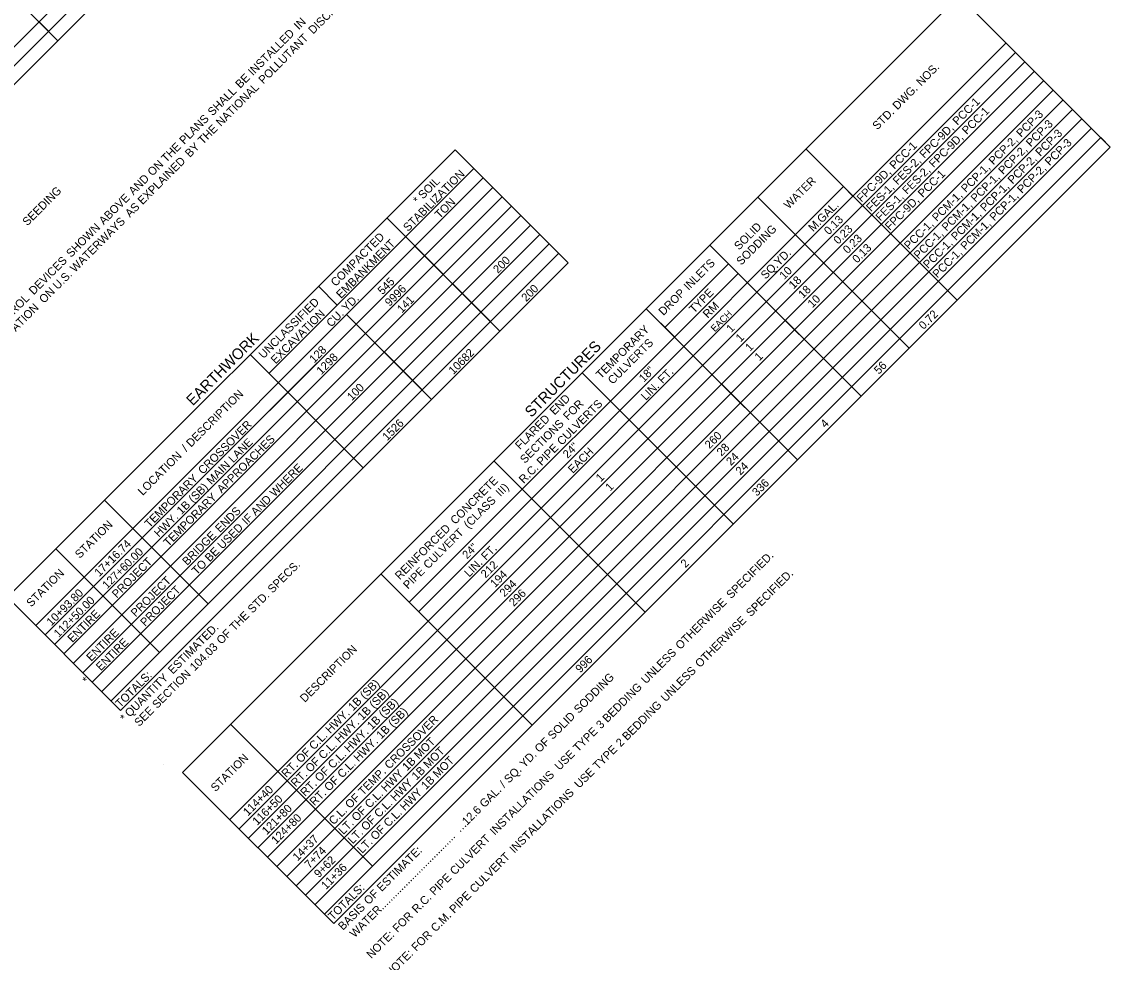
# Model space of a CAD drawing. Extents: x 1675667 to 1681231, y 227227 to 232694.
# Drawn here: x 1677364 to 1678160, y 228402 to 229090 of the extents above; entities that cross this region are included whole.
import ezdxf

# ---------------------------------------------------------------- set-up
doc = ezdxf.new("R2010")
doc.units = 0
doc.layers.add('Default', color=7, linetype='Continuous')

msp = doc.modelspace()

# ---------------------------------------------------------------- linework, layer by layer
at = {"layer": 'Default'}
for p, q in [((1677141.59, 228854.76), (1677970.88, 229684.24)), ((1677148.49, 228847.87), (1677977.77, 229677.35)), ((1677155.38, 228840.97), (1677984.67, 229670.46)), ((1677390.11, 229075.75), (1677291.16, 229174.67)), ((1677481.33, 228540.47), (1678049.35, 229108.63)), ((1678160.02, 228997.99), (1678049.35, 229108.63)), ((1677390.11, 229075.75), (1677376.32, 229089.54)), ((1677515.81, 228506.01), (1678083.83, 229074.17)), ((1677971.81, 228962.12), (1678083.83, 229074.17)), ((1677522.7, 228499.11), (1678090.72, 229067.27)), ((1677529.6, 228492.22), (1678097.62, 229060.38)), ((1677985.6, 228948.33), (1678097.62, 229060.38)), ((1677536.49, 228485.33), (1678104.51, 229053.49)), ((1677543.39, 228478.43), (1678111.41, 229046.59)), ((1677550.28, 228471.54), (1678118.3, 229039.7)), ((1677557.52, 228464.3), (1678125.54, 229032.46)), ((1677564.42, 228457.41), (1678132.44, 229025.57)), ((1678013.52, 228920.41), (1678125.54, 229032.46)), ((1678020.42, 228913.52), (1678132.44, 229025.57)), ((1677571.31, 228450.51), (1678139.33, 229018.67)), ((1678027.31, 228906.63), (1678139.33, 229018.67)), ((1677578.21, 228443.62), (1678146.23, 229011.78)), ((1678034.21, 228899.73), (1678146.23, 229011.78)), ((1677585.1, 228436.73), (1678153.12, 229004.89)), ((1678160.02, 228997.99), (1678153.12, 229004.89)), ((1677353.22, 228668.55), (1677680.66, 228996.07)), ((1677592, 228429.83), (1678160.02, 228997.99)), ((1677763.4, 228913.35), (1677680.66, 228996.07)), ((1677763.4, 228913.35), (1677680.66, 228996.07)), ((1678048, 228885.95), (1677937.33, 228996.59)), ((1677544.52, 228832.31), (1677694.45, 228982.28)), ((1677373.91, 228647.87), (1677701.35, 228975.39)), ((1677380.8, 228640.98), (1677708.24, 228968.5)), ((1677387.7, 228634.08), (1677715.14, 228961.6)), ((1677451.8, 228712), (1677708.24, 228968.5)), ((1677801.19, 228805.25), (1677964.91, 228969.01)), ((1677971.81, 228962.12), (1677964.91, 228969.01)), ((1677394.59, 228627.19), (1677722.03, 228954.71)), ((1678012.84, 228850.78), (1677902.17, 228961.42)), ((1678012.84, 228850.78), (1677902.17, 228961.42)), ((1677401.49, 228620.3), (1677728.93, 228947.82)), ((1677713.42, 228863.36), (1677630.68, 228946.08)), ((1677408.38, 228613.4), (1677735.82, 228940.92)), ((1677415.28, 228606.51), (1677742.72, 228934.03)), ((1677422.17, 228599.62), (1677749.61, 228927.14)), ((1677706.53, 228870.25), (1677651.37, 228925.4)), ((1677977.69, 228815.62), (1677867.02, 228926.26)), ((1677429.07, 228592.72), (1677756.51, 228920.24)), ((1677706.53, 228870.25), (1677756.51, 228920.24)), ((1677435.96, 228585.83), (1677763.4, 228913.35)), ((1677834.28, 228865.93), (1677880.81, 228912.47)), ((1677647.12, 228664.94), (1677887.7, 228905.58)), ((1677794.3, 228812.15), (1677887.7, 228905.58)), ((1677977.69, 228815.62), (1677887.7, 228905.58)), ((1677594.5, 228882.3), (1677580.7, 228896.09)), ((1678048, 228885.95), (1678041.1, 228892.84)), ((1677663.45, 228813.37), (1677601.39, 228875.41)), ((1677656.55, 228820.26), (1677601.39, 228875.41)), ((1677841.17, 228859.03), (1677820.49, 228879.71)), ((1677931.15, 228769.07), (1677820.49, 228879.71)), ((1677656.55, 228820.26), (1677706.53, 228870.25)), ((1677654.02, 228658.04), (1677848.07, 228852.14)), ((1677613.47, 228763.38), (1677530.73, 228846.1)), ((1677931.15, 228769.07), (1677854.96, 228845.25)), ((1677884.28, 228722.19), (1677773.61, 228832.83)), ((1677801.19, 228805.25), (1677794.3, 228812.15)), ((1677884.28, 228722.19), (1677808.09, 228798.36)), ((1677736.74, 228740.78), (1677709.16, 228768.36)), ((1677819.83, 228657.72), (1677709.16, 228768.36)), ((1677500.07, 228663.74), (1677424.22, 228739.57)), ((1677819.83, 228657.72), (1677743.63, 228733.89)), ((1677500.07, 228663.74), (1677444.91, 228718.89)), ((1677416.3, 228676.49), (1677451.8, 228712)), ((1677464.57, 228628.23), (1677388.72, 228704.06)), ((1677464.57, 228628.23), (1677409.41, 228683.38)), ((1677737.1, 228574.98), (1677626.44, 228685.62)), ((1677647.12, 228664.94), (1677626.44, 228685.62)), ((1677435.96, 228585.83), (1677353.22, 228668.55)), ((1677435.96, 228585.83), (1677353.22, 228668.55)), ((1677737.1, 228574.98), (1677730.21, 228581.87)), ((1677620.26, 228471.89), (1677516.49, 228575.64)), ((1677467.54, 228545.99), (1677467.54, 228545.99)), ((1677592, 228429.83), (1677481.33, 228540.47)), ((1677592, 228429.83), (1677481.33, 228540.47)), ((1677620.26, 228471.89), (1677550.96, 228541.17))]:
    msp.add_line(p, q, dxfattribs=at)

# ---------------------------------------------------------------- texts
for s, height, p in [(' DISCHARGE', 6, (1677575.35, 229078.64)), (' IN', 6, (1677564.79, 229081.86)), (' INSTALLED', 6, (1677531.18, 229048.25)), (' POLLUTANT', 6, (1677538.92, 229042.19)), (' NOS.', 6, (1678020.07, 229040.62)), (' BE', 6, (1677521.94, 229039.01)), (' NATIONAL', 6, (1677507.84, 229011.11)), (' DWG.', 6, (1678002.7, 229023.25)), (' SHALL', 6, (1677501.73, 229018.79)), (' PCC-1', 6, (1678046.61, 229012.01)), (' PCC-1', 6, (1678053.5, 229005.12)), (' PLANS', 6, (1677480.95, 228998.01)), ('STD.', 6, (1677989.6, 229010.15)), (' PCP-3', 6, (1678093.26, 229003.17)), (' PCP-3', 6, (1678100.33, 228996.1)), (' THE', 6, (1677494.65, 228997.92)), (' FPC-9D,', 6, (1678022.44, 228987.83)), (' PCP-3', 6, (1678107.22, 228989.21)), (' THE', 6, (1677467.77, 228984.82)), (' BY', 6, (1677485.14, 228988.41)), (' PCC-1', 6, (1678000.59, 228979.77)), (' FPC-9D,', 6, (1678029.33, 228980.94)), (' PCP-2,', 6, (1678073.04, 228982.94)), (' PCP-3', 6, (1678114.12, 228982.32)), (' PCP-2,', 6, (1678080.11, 228975.88)), (' EXPLAINED', 6, (1677450.54, 228953.8)), (' ON', 6, (1677457.71, 228974.76)), (' FES-2,', 6, (1678002.88, 228968.27)), (' PCP-2,', 6, (1678087, 228968.98)), ('STABILIZATION', 6, (1677646.29, 228935.81)), ('FPC-9D,', 6, (1677978.07, 228957.24)), (' FES-2,', 6, (1678009.77, 228961.37)), (' PCC-1', 6, (1678021.27, 228959.09)), (' PCP-1,', 6, (1678052.82, 228962.72)), (' PCP-2,', 6, (1678093.9, 228962.09)), (' AND', 6, (1677443.87, 228960.92)), (' SOIL', 6, (1677655.69, 228957.94)), ('WATER', 6, (1677924.81, 228952.24)), (' PCP-1,', 6, (1678059.89, 228955.65)), (' PCP-1,', 6, (1678066.78, 228948.76)), (' SEEDING', 6, (1677366.2, 228938.39)), (' ABOVE', 6, (1677422.11, 228939.15)), ('FES-1,', 6, (1677984.96, 228950.35)), ('FES-1,', 6, (1677991.86, 228943.45)), (' PCM-1,', 6, (1678031.62, 228941.51)), (' PCP-1,', 6, (1678073.68, 228941.87)), (' AS', 6, (1677441.29, 228944.55)), ('*', 6, (1677653.51, 228955.76)), ('TON', 6, (1677669.49, 228945.22)), ('M.GAL.', 6, (1677942.74, 228935.69)), ('FPC-9D,', 6, (1677998.75, 228936.56)), (' PCM-1,', 6, (1678038.68, 228934.44)), (' WATERWAYS', 6, (1677401.1, 228904.34)), ('0.13', 6, (1677954.17, 228933.34)), (' PCM-1,', 6, (1678045.58, 228927.55)), (' SHOWN', 6, (1677398.23, 228915.27)), ('SOLID', 6, (1677888.42, 228922.2)), ('SODDING', 6, (1677890.04, 228911.09)), ('0.23', 6, (1677961.06, 228926.44)), ('PCC-1,', 6, (1678012.71, 228922.6)), (' PCM-1,', 6, (1678052.47, 228920.66)), ('COMPACTED', 6, (1677593.32, 228895.55)), ('EMBANKMENT', 6, (1677597.29, 228886.8)), ('0.23', 6, (1677967.96, 228919.55)), ('PCC-1,', 6, (1678019.78, 228915.54)), ('0.13', 6, (1677974.85, 228912.66)), ('PCC-1,', 6, (1678026.68, 228908.64)), ('PCC-1,', 6, (1678033.57, 228901.75)), (' DEVICES', 6, (1677370.87, 228887.9)), ('200', 6, (1677712.08, 228905.08)), (' INLETS', 6, (1677849.98, 228891.18)), ('SQ.YD.', 6, (1677907.9, 228900.85)), (' U.S.', 6, (1677388.44, 228891.68)), ('10', 6, (1677921.49, 228900.65)), ('545', 6, (1677627.6, 228889.53)), ('18', 6, (1677928.37, 228893.75)), (' ON', 6, (1677378.39, 228881.63)), ('9996', 6, (1677632.87, 228881.01)), ('200', 6, (1677732.77, 228884.4)), ('DROP', 6, (1677833.13, 228874.32)), ('TYPE', 6, (1677855.52, 228876.03)), ('18', 6, (1677935.27, 228886.85)), (' SEDIMENTATION', 6, (1677328.49, 228831.71)), (' CONTROL', 6, (1677340.46, 228857.48)), ('UNCLASSIFIED', 6, (1677540.54, 228842.76)), (' YD.', 6, (1677599.88, 228875.6)), ('141', 6, (1677641.82, 228876.17)), ('RM', 6, (1677865.61, 228872.34)), ('10', 6, (1677942.17, 228879.97)), ('EXCAVATION', 6, (1677549.46, 228838.96)), ('CU.', 6, (1677590.08, 228865.8)), ('EACH', 5, (1677870.71, 228862.41)), ('0.72', 6, (1678023.48, 228864.07)), ('TEMPORARY', 6, (1677787.39, 228828.04)), ('1', 6, (1677882.69, 228861.85)), ('EARTHWORK', 8, (1677488.83, 228808.18)), ('1', 6, (1677889.59, 228854.95)), ('128', 6, (1677577.64, 228839.56)), ('10682', 6, (1677679.5, 228831.12)), ('STRUCTURES', 8, (1677736.53, 228799.73)), ('CULVERTS', 6, (1677796.04, 228823.97)), ('1', 6, (1677896.49, 228848.06)), ('1298', 6, (1677582.88, 228831.02)), ('1', 6, (1677903.38, 228841.17)), ('18"', 6, (1677818.75, 228825.47)), (' FT.', 6, (1677831.01, 228822.98)), ('56', 6, (1677990.75, 228831.33)), (' DESCRIPTION', 6, (1677485.99, 228776.42)), ('100', 6, (1677605.23, 228812)), ('LIN.', 6, (1677820.22, 228812.19)), (' END', 6, (1677751.89, 228799.96)), (' CULVERTS', 6, (1677757.25, 228777.74)), (' FOR', 6, (1677761.79, 228796.07)), (' CROSSOVER', 6, (1677494.66, 228756.56)), ('1526', 6, (1677631.12, 228782.74)), ('FLARED', 6, (1677728.15, 228776.21)), ('SECTIONS', 6, (1677731.78, 228766.06)), ('4', 6, (1677951.51, 228792.09)), (' APPROACHES', 6, (1677508.45, 228742.78)), ('260', 6, (1677866.94, 228776.8)), (' /', 6, (1677482.69, 228773.12)), (' LANE', 6, (1677516.85, 228764.97)), (' PIPE', 6, (1677742.39, 228762.87)), ('24"', 6, (1677763.09, 228769.79)), ('28', 6, (1677875.65, 228771.37)), ('LOCATION', 6, (1677452.21, 228742.64)), ('EACH', 6, (1677766.84, 228758.8)), ('24', 6, (1677882.55, 228764.49)), (' MAIN', 6, (1677500.88, 228748.99)), (' WHERE', 6, (1677547.13, 228740.09)), ('R.C.', 6, (1677730.94, 228751.43)), ('24', 6, (1677889.45, 228757.59)), ('TEMPORARY', 6, (1677457.16, 228719.05)), (' CONCRETE', 6, (1677679.22, 228719.85)), ('1', 6, (1677787.22, 228752.56)), ('336', 6, (1677901.55, 228742.12)), (' (SB)', 6, (1677487.59, 228735.7)), (' III)', 6, (1677712.4, 228740.3)), ('1', 6, (1677794.12, 228745.67)), ('TEMPORARY', 6, (1677470.95, 228705.26)), (' 1B', 6, (1677479.01, 228727.12)), (' AND', 6, (1677533.28, 228726.24)), (' (CLASS', 6, (1677688.98, 228716.88)), (' ENDS', 6, (1677507.15, 228713.89)), ('STATION', 6, (1677406.17, 228696.58)), ('HWY.', 6, (1677464.05, 228712.16)), (' IF', 6, (1677526.64, 228719.6)), ('BRIDGE', 6, (1677484.74, 228691.48)), (' USED', 6, (1677508.84, 228701.79)), ('REINFORCED', 6, (1677640.32, 228680.94)), (' CULVERT', 6, (1677659.46, 228687.35)), ('17+16.74', 6, (1677420.43, 228683.27)), ('24"', 6, (1677689.5, 228696.19)), ('127+60.00', 6, (1677426.16, 228674.25)), (' BE', 6, (1677499.6, 228692.55)), (' FT.', 6, (1677701.75, 228693.7)), (' SPECIFIED.', 6, (1677881.12, 228665.56)), ('PROJECT', 6, (1677433.22, 228667.53)), ('TO', 6, (1677491.64, 228684.58)), (' SPECS.', 6, (1677545.57, 228669.58)), ('PIPE', 6, (1677646.24, 228674.14)), ('LIN.', 6, (1677690.97, 228682.91)), ('212', 6, (1677703.06, 228682.17)), ('2', 6, (1677849.23, 228689.78)), ('STATION', 6, (1677370.67, 228661.07)), ('PROJECT', 6, (1677447.01, 228653.74)), ('194', 6, (1677709.94, 228675.26)), (' SPECIFIED.', 6, (1677895.52, 228652.39)), ('PROJECT', 6, (1677453.91, 228646.85)), ('294', 6, (1677716.83, 228668.37)), ('10+93.80', 6, (1677385.41, 228647.28)), ('112+50.00', 6, (1677390.66, 228638.74)), (' STD.', 6, (1677530.94, 228654.94)), ('296', 6, (1677723.72, 228661.46)), (' OTHERWISE', 6, (1677843.89, 228628.33)), ('ENTIRE', 6, (1677400.78, 228635.08)), (' THE', 6, (1677517.75, 228641.76)), (' OTHERWISE', 6, (1677858.3, 228615.15)), ('ENTIRE', 6, (1677414.57, 228621.29)), (' ESTIMATED.', 6, (1677472.62, 228610.41)), (' OF', 6, (1677508.15, 228632.15)), ('ENTIRE', 6, (1677421.47, 228614.4)), (' 104.03', 6, (1677488.65, 228612.65)), ('DESCRIPTION', 6, (1677570.8, 228591.25)), (' UNLESS', 6, (1677818.84, 228603.27)), ('996', 6, (1677772.3, 228612.83)), ('TOTALS:', 6, (1677435.8, 228587.37)), ('QUANTITY', 6, (1677442.7, 228580.47)), (' SECTION', 6, (1677461.14, 228585.13)), (' SODDING', 6, (1677769.61, 228581.61)), (' UNLESS', 6, (1677833.24, 228590.09)), ('*', 6, (1677411.64, 228604.57)), (' (SB)', 6, (1677613.03, 228592.12)), (' BEDDING', 6, (1677790.56, 228574.98)), (' 1B', 6, (1677604.46, 228583.54)), (' (SB)', 6, (1677619.93, 228585.23)), ('SEE', 6, (1677449.59, 228573.58)), (' 1B', 6, (1677611.35, 228576.65)), (' (SB)', 6, (1677626.82, 228578.33)), (' (SB)', 6, (1677633.72, 228571.44)), (' BEDDING', 6, (1677804.96, 228561.8)), ('*', 6, (1677439.22, 228577)), (' HWY.', 6, (1677587.85, 228566.93)), (' 1B', 6, (1677618.25, 228569.75)), (' CROSSOVER', 6, (1677631.07, 228540.86)), (' SOLID', 6, (1677750.49, 228562.49)), (' HWY.', 6, (1677594.75, 228560.04)), (' HWY.', 6, (1677601.64, 228553.15)), (' 1B', 6, (1677625.14, 228562.86)), (' TYPE', 6, (1677769.07, 228553.49)), (' 3', 6, (1677785.89, 228570.31)), (' C.L.', 6, (1677575.86, 228554.93)), (' HWY.', 6, (1677608.54, 228546.25)), (' MOT', 6, (1677652.59, 228548.25)), (' OF', 6, (1677740.89, 228552.88)), (' 2', 6, (1677800.33, 228557.18)), (' OF', 6, (1677566.25, 228545.33)), (' C.L.', 6, (1677582.75, 228548.04)), (' MOT', 6, (1677659.49, 228541.36)), (' USE', 6, (1677755.55, 228539.97)), (' TYPE', 6, (1677783.52, 228540.36)), ('STATION', 6, (1677505.5, 228525.93)), ('RT.', 6, (1677557.22, 228536.29)), (' OF', 6, (1677573.15, 228538.43)), (' C.L.', 6, (1677589.65, 228541.15)), (' 1B', 6, (1677644.01, 228539.67)), (' MOT', 6, (1677666.38, 228534.47)), (' YD.', 6, (1677729.88, 228541.87)), ('RT.', 6, (1677564.12, 228529.4)), (' OF', 6, (1677580.04, 228531.54)), (' C.L.', 6, (1677596.54, 228534.25)), (' TEMP.', 6, (1677611.82, 228521.61)), (' HWY', 6, (1677628.58, 228524.24)), (' 1B', 6, (1677650.91, 228532.78)), (' INSTALLATIONS', 6, (1677708.1, 228492.51)), (' SQ.', 6, (1677718.54, 228530.52)), (' USE', 6, (1677770, 228526.84)), ('RT.', 6, (1677571.01, 228522.51)), (' OF', 6, (1677586.94, 228524.65)), (' HWY', 6, (1677635.48, 228517.35)), (' 1B', 6, (1677657.8, 228525.89)), (' /', 6, (1677715.24, 228527.23)), ('114+40', 6, (1677529.13, 228508.19)), ('116+50', 6, (1677536.02, 228501.3)), ('RT.', 6, (1677577.91, 228515.61)), (' OF', 6, (1677602.22, 228512.01)), (' C.L.', 6, (1677616.59, 228512.24)), (' HWY', 6, (1677642.37, 228510.45)), (' GAL.', 6, (1677700.61, 228512.59)), (' INSTALLATIONS', 6, (1677722.55, 228479.38)), ('121+80', 6, (1677542.92, 228494.41)), (' OF', 6, (1677606.98, 228502.63)), (' C.L.', 6, (1677623.48, 228505.35)), ('12.6', 6, (1677689.35, 228501.33)), ('124+80', 6, (1677549.81, 228487.51)), ('C.L.', 6, (1677591.87, 228501.65)), (' OF', 6, (1677613.88, 228495.74)), (' C.L.', 6, (1677630.38, 228498.46)), ('LT.', 6, (1677598.94, 228494.59)), (' OF', 6, (1677620.77, 228488.85)), ('…', 6, (1677684.12, 228496.09)), ('14+37', 6, (1677565.42, 228475.19)), ('LT.', 6, (1677605.83, 228487.69)), (' WATER..................................', 6, (1677605.63, 228417.58)), (' CULVERT', 6, (1677678.91, 228463.31)), ('7+74', 6, (1677574.14, 228469.79)), ('LT.', 6, (1677612.73, 228480.8)), (' ESTIMATE:', 6, (1677625.49, 228451.24)), ('9+62', 6, (1677581.05, 228462.91)), (' CULVERT', 6, (1677693.36, 228450.18)), ('11+36', 6, (1677586.27, 228454.34)), (' PIPE', 6, (1677664.07, 228448.46)), ('TOTALS:', 6, (1677591.36, 228431.85)), (' OF', 6, (1677615.89, 228441.64)), (' PIPE', 6, (1677678.52, 228435.33)), ('BASIS', 6, (1677598.73, 228424.48)), (' R.C.', 6, (1677651.09, 228435.48)), (' FOR', 6, (1677637.01, 228421.4)), (' C.M.', 6, (1677664.88, 228421.69)), ('NOTE:', 6, (1677619.42, 228403.8)), (' FOR', 6, (1677650.8, 228407.61)), ('NOTE:', 6, (1677633.21, 228390.01))]:
    msp.add_text(s, height=height, rotation=45.00703, dxfattribs=at).set_placement(p)

doc.saveas('drawing.dxf')
